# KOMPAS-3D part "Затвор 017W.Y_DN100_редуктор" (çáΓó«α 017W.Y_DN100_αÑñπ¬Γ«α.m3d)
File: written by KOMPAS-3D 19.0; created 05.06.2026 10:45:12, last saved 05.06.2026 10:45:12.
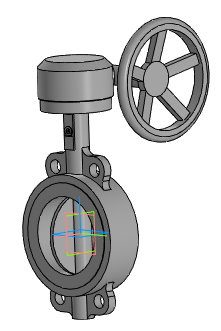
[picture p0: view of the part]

Document properties: Автор: Энергия; Полное имя файла: ..\..\..\3d для проектировщиков\x.x Тип 017W.Y(S) Затвор дисковый поворотный межфланцевый\Затвор 017W.Y(S)_DN50-DN1200_редуктор\Затвор 017W.Y_DN100_редуктор.a3d

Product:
- Part/product: Затвор 017W.Y_DN100_редуктор
    Масса: 10.8638

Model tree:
1. Операция без истории:1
